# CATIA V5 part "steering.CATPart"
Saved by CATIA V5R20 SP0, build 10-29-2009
Part number: spd_sensor
Bounding box of the stored display mesh (mm): x -17.853 to 46.793, y -24.787 to 0, z 0 to 5.37
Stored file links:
  C:\Users\user\OneDrive\바탕 화면\지혜 카티아\spd_sensor.CATPart
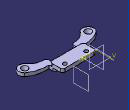
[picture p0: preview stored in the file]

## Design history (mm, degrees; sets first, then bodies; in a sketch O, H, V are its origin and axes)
Body1 (main body)
  Sketch1 on xy-plane, origin (0, 0, 0), H (1, 0, 0), V (0, 1, 0)
    line L1 (0, 0) -> (28.94, 0)
    line L2 (28.94, 0) -> (28.94, -11.7)
    line L3 (25.275, -11.7) -> (3.665, -11.7)
    line L4 (0, -11.7) -> (0, 0)
    point P2 (28.94, -11.7)
    point P3 (0, -11.7)
    line L5 (3.665, -11.7) -> (3.665, -17.7)
    point P5 (3.665, -17.7)
    arc A1 centre (-12.955, -19.84) radius 4.96 from (-16.298, -16.1759) to (-8.6255, -22.2602) ccw
    point P6 (-12.955, -19.84)
    spline S1 through (-8.6255, -22.2602) (-7.5055, -21.0064) (3.665, -17.7)
    spline S2 through (-16.298, -16.1759) (-12.1075, -13.7698) (0, -11.7)
    point P8 (-8.6255, -22.2602)
    point P9 (37.5655, -22.2602)
    point P10 (45.238, -16.1759)
    arc A2 centre (41.895, -19.84) radius 4.96 from (45.238, -16.1759) to (37.5655, -22.2602) cw
    spline S3 through (37.5655, -22.2602) (36.4455, -21.0064) (25.275, -17.7)
    point P12 (45.238, -16.1759)
    spline S4 through (45.238, -16.1759) (41.0475, -13.7698) (28.94, -11.7)
    point P13 (25.275, -17.7)
    line L6 (25.275, -11.7) -> (25.275, -17.7)
    point P15 (-8.6255, -22.2602)
    point P16 (3.665, -17.7)
    point P17 (-16.298, -16.1759)
    point P18 (0, -11.7)
    point P19 (25.275, -17.7)
    point P20 (37.5655, -22.2602)
    point P23 (28.94, -11.7)
    length L2 = 11.7
    length L1 = 28.94
    distance L5 P3 = 3.665
    length L5 = 6
    radius A1 = 4.96
    distance P6 L3 = 8.14
    length L6 = 6
    horizontal: L1 H, L3 H
    vertical: L2 V, L4 V, L5 V
    coincidence: P15 A1, P16 P5, P17 A1, P18 P3, P2 L3, P3 L3, P8 P15, P9 P20, P2 P23, P10 P12, P19 P13
  Pad1: profile Sketch1, direction (0, 0, 1), length 5.37
  Sketch2 on xy-plane, origin (0, 0, 0), H (1, 0, 0), V (0, 1, 0)
    line L1 (35.9009, 2.3248) -> (-6.1386, 2.3248)
    line L2 (-6.1386, 2.3248) -> (-6.1386, -6.52)
    line L3 (-6.1386, -6.52) -> (35.9009, -6.52)
    line L4 (35.9009, -6.52) -> (35.9009, 2.3248)
    reference projected point E1 (25.275, -17.7) from vertex [face of Pad1 from Sketch1.S3 | start face of Pad1 | face of Pad1 from Sketch1.L6]
    distance L3 E1 = 11.18
    horizontal: L1 H, L3 H
    vertical: L2 V, L4 V
  Pocket1: profile Sketch2, direction (0, 0, 1), length 2.3
  Sketch3 on end face of Pad1, origin (0, 0, 5.37), H (1, 0, 0), V (0, 1, 0)
    line L1 (-22.9882, -11.2) -> (53.8573, -11.2)
    line L2 (53.8573, -11.2) -> (53.8573, -30.4322)
    line L3 (53.8573, -30.4322) -> (-22.9882, -30.4322)
    line L4 (-22.9882, -30.4322) -> (-22.9882, -11.2)
    reference projected line E1 (3.665, -11.7) -> (25.275, -11.7) from edge [face of Pad1 from Sketch1.L3 | end face of Pad1]
    distance L1 E1 = 0.5
    horizontal: L1 H, L3 H
    vertical: L2 V, L4 V
  Pocket2: profile Sketch3, direction (0, 0, -1), length 2.5
  Sketch4 on end face of Pocket2, origin (-13.1601, -20.3556, 2.87), H (1, 0, 0), V (0, 1, 0)
    point P1 (0.3094, 0.6446)
  Hole1: placed by Sketch4, at (-12.8508, -19.711, 2.87) direction (0, 0, -1), diameter 3, through (limit type 6), countersink depth 2.87, countersink angle 50
  Sketch5 on end face of Pad1, origin (0, 0, 5.37), H (1, 0, 0), V (0, 1, 0)
  Plane1: type Offset, RefPlane yz-plane, Offset 14.47
  Mirror1: of Hole1, about Plane1
  Sketch6 on end face of Pad1, origin (17.019, -8.3219, 5.37), H (1, 0, 0), V (0, 1, 0)
    point P1 (-11.799, 4.9819)
    point P2 (-11.799, 4.9819)
    coincidence: P1 P2
  Hole2: placed by Sketch6, at (5.22, -3.34, 5.37) direction (0, 0, -1), diameter 3.34, through (limit type 6)
  Mirror2: of Hole2, about Plane1
  Fillet1: radius 2, on edge [face of Pad1 from Sketch1.L5 | face of Pad1 from Sketch1.S1]
  Fillet2: radius 2, on edge [face of Pad1 from Sketch1.S3 | face of Pad1 from Sketch1.L6]
  Fillet3: radius 2, on edge [face of Pad1 from Sketch1.L4 | face of Pad1 from Sketch1.L1]
  Fillet4: radius 2, on edge [face of Pad1 from Sketch1.L1 | face of Pad1 from Sketch1.L2]
  Fillet5: radius 2, on edge [face of Pad1 from Sketch1.L4 | face of Pocket2 from Sketch3.L1]
  Fillet6: radius 2, on edge [face of Pocket2 from Sketch3.L1 | face of Pad1 from Sketch1.L2]
  Fillet7: radius 2, on edge [face of Pad1 from Sketch1.L4 | face of Pocket1 from Sketch2.L3]
  Fillet8: radius 2, on edge [face of Pocket1 from Sketch2.L3 | face of Pad1 from Sketch1.L2]
  Fillet9: radius 1, on edge [face of Pad1 from Sketch1.L3 | face of Pad1 from Sketch1.L5]
  Fillet10: radius 1, on edge [face of Pad1 from Sketch1.L6 | face of Pad1 from Sketch1.L3]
